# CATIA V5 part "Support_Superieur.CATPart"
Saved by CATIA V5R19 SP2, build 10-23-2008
Part number: Support_Superieur
Bounding box of the stored display mesh (mm): x 0 to 1, y -8 to 77.896, z -11.452 to 6.708
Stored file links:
  G:\EU_thinkMotion\CFAO_2010\MMS_groupe3\MMS_groupe3\A reprendre\lletoffe\lletoffe_Thinkmotion_CFAO\Modèle Catia\Support_Superieur.CATPart
  E:\CFAO\Last Catia\Support superieur.CATPart
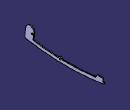
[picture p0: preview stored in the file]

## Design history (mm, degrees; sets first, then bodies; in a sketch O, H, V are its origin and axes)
Parameters
  Epaisseur = 1 mm
Set1
  Point1: (0, 30.2, -8.3)
  Point2: (1, 30.2, -8.3)
  Line1: type PtPt, FirstPoint Point1, SecondPoint Point2, Start 10, End 10
  Point3: (0, 0, 0)
  Point4: (1, 0, 0)
  Line2: type PtPt, FirstPoint Point3, SecondPoint Point4, Start 10, End 10
  Plane1: type Offset, RefPlane yz-plane, Offset 1 {= Epaisseur}
  Sketch1 on yz-plane, origin (0, 0, 0), H (0, 1, 0), V (0, 0, 1)
    circle A1 centre (0, 0) radius 1
    arc A2 centre (37, -6) radius 45 from (-7.0473, 3.2106) to (-8, -6) ccw
    arc A3 centre (-6.2499, -6) radius 1.75 from (-7.9999, -6) to (-6.5548, -7.7232) ccw
    point P1 (-6.2499, -6)
    arc A4 centre (1.7145, -4.6735) radius 1 from (0.7297, -4.4998) to (1.5728, -5.6634) ccw
    line L1 (1.7891, 1.5081) -> (0.7297, -4.4998)
    point P3 (26.4176, -8.3)
    construction line L2 through (0.0245, 0) direction (1, 0)
    construction line L3 through (0, -0.1183) direction (0, 1)
    arc A5 centre (32.9724, -7.1537) radius 1 from (32.0482, -7.5358) to (32.9562, -8.1536) ccw
    arc A6 centre (27.494, -7.0048) radius 1 from (27.4558, -8.004) to (28.396, -7.4365) ccw
    arc A7 centre (77.3965, -7.7545) radius 0.5 from (77.4774, -8.2479) to (77.4298, -7.2556) ccw
    arc A8 centre (77.4965, -6.2578) radius 1 from (76.4965, -6.2578) to (77.4298, -7.2556) ccw
    arc A9 centre (75.4965, -4.1994) radius 1 from (75.4616, -3.2) to (76.4965, -4.1994) cw
    line L4 (76.4965, -4.1994) -> (76.4965, -6.2578)
    arc A10 centre (68.2465, -4.966) radius 1.25 from (68.4035, -6.2061) to (69.4965, -4.966) ccw
    line L5 (69.4965, -4.966) -> (69.4965, -4.374)
    arc A11 centre (70.4965, -4.374) radius 1 from (69.4965, -4.374) to (70.4616, -3.3746) cw
    arc A12 centre (37, 238.4535) radius 250 from (-6.5548, -7.7232) to (77.4774, -8.2479) ccw
    arc A13 centre (37, 241.8137) radius 250 from (32.9562, -8.1536) to (68.4035, -6.2061) ccw
    arc A14 centre (37, 241.8137) radius 250 from (1.5728, -5.6634) to (27.4558, -8.004) ccw
    arc A15 centre (-2.6426, 2.2895) radius 4.5 from (1.7891, 1.5081) to (-7.0473, 3.2106) ccw
    point P5 (37, -6)
    point P6 (77.3965, -7.7545)
    point P7 (77.4965, -6.2578)
    point P8 (37, 241.8137)
    axis line L6 (37, 241.8137) -> (37, 238.4535)
    point P9 (0, 0)
    point P17 (75.4616, -3.2)
    reference projected point E1 (0, 0) from Line2
    circle A16 centre (30.2, -8.3) radius 1
    arc A17 centre (30.2, -8.3) radius 2 from (32.0482, -7.5358) to (28.396, -7.4365) ccw
    reference projected point E2 (30.2, -8.3) from Line1
    line L7 (70.4616, -3.3746) -> (75.4616, -3.2)
    point P41 (75.4616, -3.2)
    radius A1 = 1
    radius A3 = 1.75
    radius A4 = 1
    distance L2 P3 = 8.3
    radius A5 = 1
    radius A6 = 1
    radius A7 = 0.5
    distance L4 L5 = 7
    radius A11 = 1
    radius A9 = 1
    radius A10 = 1.25
    radius A13 = 250
    radius A12 = 250
    radius A2 = 45
    radius A14 = 250
    radius A15 = 4.5
    angle L1 L3 = 10
    distance P1 L2 = 6
    distance P5 L3 = 37
    distance P6 L4 = 0.9
    distance P7 L4 = 1
    distance L2 P8 = 241.8137
    distance L3 P8 = 37
    distance P9 L1 = 1.5
    angle L1 V = 10
    distance L3 L4 = 76.4965
    distance P1 L3 = 6.2499
    radius A16 = 1
    radius A17 = 2
    angle L7 L2 = 2
    distance P17 L2 = 3.2
    tangency: A3 A2, L1 A4, A8 A7, L4 A9, L5 A10, A11 L5, L4 A8, A7 A12, A3 A12, A2 A15, A10 A13, A14 A4, A14 A6, A5 A13, L1 A15, A17 A5, A17 A6, L7 A9, L7 A11
    vertical: L5 L3, L6 L3
    coincidence: P9 L3, P9 L2, P41 A9, P17 L7
    perpendicularity: L2 L3
    concentricity: A1 E1, A17 A16, A16 E2
Body1 (main body)
  Pad1: profile Sketch1, direction (1, 0, 0), up to Plane1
